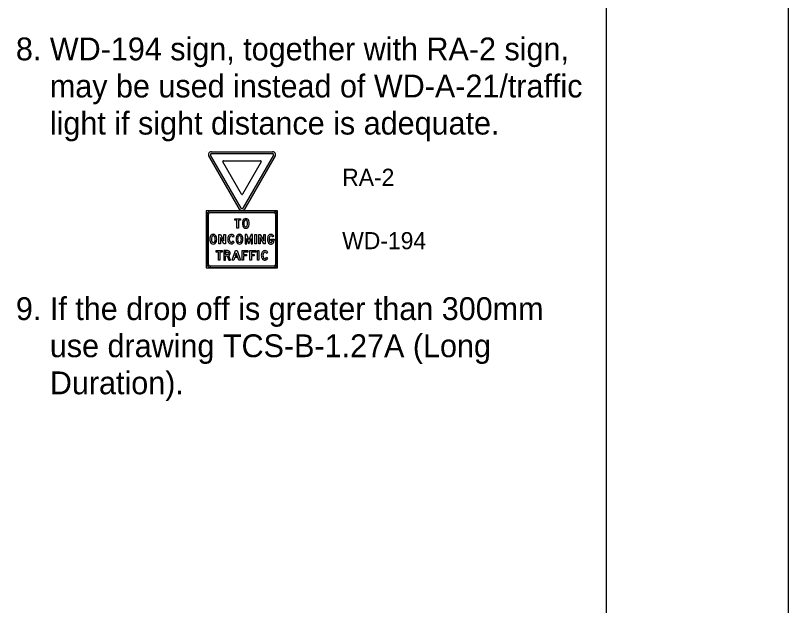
# Model space of a CAD drawing. Extents: x 1062 to 1288, y 239 to 518.
# Drawn here: x 1206.3 to 1287.6, y 312.1 to 374.1 of the extents above; entities that cross this region are included whole.
import ezdxf

# ---------------------------------------------------------------- set-up
doc = ezdxf.new("R2010")
doc.units = 0
for name, color, linetype in [('Level 1', 7, 'Continuous'), ('Level 17', 7, 'Continuous'), ('Level 60', 7, 'Continuous'), ('Level 61', 7, 'Continuous'), ('Level 62', 7, 'Continuous')]:
    doc.layers.add(name, color=color, linetype=linetype)

msp = doc.modelspace()

# ---------------------------------------------------------------- linework, layer by layer
at = {"layer": 'Level 1'}
for p, q in [((1226.352, 359.806), (1226.352, 359.806)), ((1233.835, 359.806), (1233.835, 359.806))]:
    msp.add_line(p, q, dxfattribs=at)
at = {"layer": 'Level 60'}
for p, q in [((1229.837, 353.769), (1226.609, 359.36)), ((1229.834, 353.743), (1226.61, 359.357)), ((1230.01, 353.869), (1226.782, 359.46)), ((1226.794, 359.623), (1226.798, 359.621)), ((1226.87, 359.807), (1226.874, 359.806)), ((1226.87, 359.806), (1233.317, 359.806)), ((1226.874, 359.806), (1233.322, 359.806)), ((1226.874, 359.606), (1233.322, 359.606)), ((1233.405, 359.46), (1230.186, 353.869)), ((1233.577, 359.357), (1230.347, 353.744)), ((1233.579, 359.36), (1230.359, 353.769)), ((1230.037, 355.338), (1228.074, 358.742)), ((1228.136, 358.849), (1232.051, 358.849)), ((1232.113, 358.742), (1230.161, 355.338)), ((1229.13, 350.849), (1229.28, 350.909)), ((1229.28, 350.329), (1229.13, 350.389)), ((1229.13, 350.389), (1229.13, 350.389)), ((1233.45, 350.899), (1233.3, 350.849)), ((1233.3, 350.849), (1233.3, 350.849)), ((1228.58, 349.009), (1228.35, 349.009)), ((1232.66, 349.149), (1232.81, 349.209)), ((1232.81, 348.629), (1232.66, 348.689)), ((1232.66, 348.689), (1232.66, 348.689))]:
    msp.add_line(p, q, dxfattribs=at)
for points in [[(1287.562, 517.932), (1071.562, 517.932), (1071.562, 238.932), (1287.562, 238.932)], [(1268.436, 507.123), (1081.562, 507.123), (1081.562, 249.741), (1268.436, 249.741)], [(1229.95, 352.769), (1229.95, 352.609), (1229.72, 352.609), (1229.72, 351.769), (1229.56, 351.769), (1229.56, 352.609), (1229.33, 352.609), (1229.33, 352.769)], [(1227.67, 350.109), (1227.67, 351.109), (1227.83, 351.109), (1228.2, 350.439), (1228.2, 351.109), (1228.36, 351.109), (1228.36, 350.109), (1228.2, 350.109), (1227.83, 350.779), (1227.83, 350.109)], [(1230.43, 350.109), (1230.59, 350.109), (1230.59, 350.699), (1230.82, 350.109), (1231.05, 350.699), (1231.05, 350.109), (1231.21, 350.109), (1231.21, 351.109), (1231.04, 351.109), (1230.82, 350.549), (1230.6, 351.109), (1230.43, 351.109)], [(1231.45, 351.109), (1231.61, 351.109), (1231.61, 350.109), (1231.45, 350.109)], [(1231.85, 350.109), (1231.85, 351.109), (1232.01, 351.109), (1232.38, 350.439), (1232.38, 351.109), (1232.54, 351.109), (1232.54, 350.109), (1232.38, 350.109), (1232.01, 350.779), (1232.01, 350.109)], [(1228, 349.409), (1228, 349.249), (1227.77, 349.249), (1227.77, 348.409), (1227.61, 348.409), (1227.61, 349.249), (1227.38, 349.249), (1227.38, 349.409)], [(1229.33, 348.679), (1229.23, 348.409), (1229.06, 348.409), (1229.4, 349.409), (1229.58, 349.409), (1229.92, 348.409), (1229.75, 348.409), (1229.65, 348.679)], [(1229.38, 348.839), (1229.6, 348.839), (1229.49, 349.159)], [(1230.72, 349.409), (1230.72, 349.249), (1230.26, 349.249), (1230.26, 349.009), (1230.56, 349.009), (1230.56, 348.849), (1230.26, 348.849), (1230.26, 348.409), (1230.1, 348.409), (1230.1, 349.409)], [(1231.54, 349.409), (1231.54, 349.249), (1231.08, 349.249), (1231.08, 349.009), (1231.37, 349.009), (1231.37, 348.849), (1231.08, 348.849), (1231.08, 348.409), (1230.92, 348.409), (1230.92, 349.409)], [(1231.72, 349.409), (1231.88, 349.409), (1231.88, 348.409), (1231.72, 348.409)]]:
    msp.add_lwpolyline(points, close=True, dxfattribs=at)
for points in [[(1233.3, 350.459), (1233.12, 350.459), (1233.12, 350.619), (1233.46, 350.619), (1233.46, 350.459)], [(1228.58, 349.409), (1228.19, 349.409), (1228.19, 348.409), (1228.35, 348.409), (1228.35, 348.849), (1228.54, 348.849)], [(1228.35, 349.009), (1228.35, 349.249), (1228.58, 349.249)], [(1228.54, 348.849), (1228.7, 348.409), (1228.88, 348.409), (1228.7, 348.879)]]:
    msp.add_lwpolyline(points, dxfattribs=at)
for centre, radius, start, end in [((1226.87, 359.507), 0.3, 90, 209.98927), ((1226.869, 359.506), 0.3, 90, 209.86734), ((1226.87, 359.507), 0.0997, 90, 209.98927), ((1233.316, 359.506), 0.3, 330.08336, 90), ((1233.321, 359.507), 0.3, 330.03077, 90), ((1233.321, 359.507), 0.0997, 330.03077, 90), ((1228.135, 358.777), 0.0716, 90, 209.98092), ((1232.051, 358.777), 0.0716, 330.17071, 90), ((1230.099, 355.373), 0.0716, 209.98036, 330.16989), ((1230.09, 353.898), 0.3, 211.17428, 328.87318), ((1230.097, 353.916), 0.3, 210.00132, 330.04133), ((1230.097, 353.916), 0.0997, 210.00132, 330.04133), ((1231.16, 352.28), 1.026, 166.05854, 180.2879), ((1231.16, 352.269), 1.026, 179.7121, 193.94146), ((1230.493, 352.45), 0.338, 90.40152, 166.9064), ((1230.493, 352.099), 0.338, 193.0936, 269.59848), ((1231.047, 352.293), 0.753, 162.59619, 181.38244), ((1231.047, 352.256), 0.753, 178.61757, 197.40381), ((1230.486, 352.46), 0.167, 88.23262, 159.96856), ((1230.486, 352.088), 0.167, 200.03143, 271.76738), ((1230.489, 352.45), 0.338, 13.0936, 89.59848), ((1230.496, 352.46), 0.167, 20.03143, 91.76738), ((1230.496, 352.088), 0.167, 268.23262, 339.96856), ((1230.489, 352.099), 0.338, 270.40152, 346.9064), ((1229.935, 352.293), 0.753, 358.61757, 17.40381), ((1229.935, 352.256), 0.753, 342.59619, 1.38244), ((1229.822, 352.28), 1.026, 359.7121, 13.94146), ((1229.822, 352.269), 1.026, 346.05854, 0.2879), ((1227.742, 350.617), 1.026, 166.05854, 180.2879), ((1227.742, 350.606), 1.026, 179.7121, 193.94146), ((1227.076, 350.787), 0.338, 90.40152, 166.9064), ((1227.076, 350.436), 0.338, 193.0936, 269.59848), ((1227.63, 350.63), 0.753, 162.59619, 181.38244), ((1227.63, 350.593), 0.753, 178.61757, 197.40381), ((1227.068, 350.798), 0.167, 88.23262, 159.96856), ((1227.068, 350.425), 0.167, 200.03143, 271.76738), ((1227.071, 350.787), 0.338, 13.0936, 89.59848), ((1227.079, 350.798), 0.167, 20.03143, 91.76738), ((1227.079, 350.425), 0.167, 268.23262, 339.96856), ((1227.071, 350.436), 0.338, 270.40152, 346.9064), ((1226.517, 350.63), 0.753, 358.61757, 17.40381), ((1226.517, 350.593), 0.753, 342.59619, 1.38244), ((1226.405, 350.617), 1.026, 359.7121, 13.94146), ((1226.405, 350.606), 1.026, 346.05854, 0.2879), ((1229.263, 350.619), 0.666, 149.79441, 180.51978), ((1229.263, 350.607), 0.666, 179.48022, 210.20559), ((1228.972, 350.791), 0.328, 21.11364, 150.27929), ((1229.229, 350.63), 0.47, 149.9866, 182.06213), ((1229.229, 350.596), 0.47, 177.93787, 210.0134), ((1228.972, 350.791), 0.168, 20.91519, 153.75348), ((1228.971, 350.432), 0.165, 205.38308, 344.75942), ((1230.497, 350.617), 1.026, 166.05854, 180.2879), ((1230.497, 350.606), 1.026, 179.7121, 193.94146), ((1229.831, 350.787), 0.338, 90.40152, 166.9064), ((1229.831, 350.436), 0.338, 193.0936, 269.59848), ((1230.385, 350.63), 0.753, 162.59619, 181.38244), ((1230.385, 350.593), 0.753, 178.61757, 197.40381), ((1229.823, 350.798), 0.167, 88.23262, 159.96856), ((1229.823, 350.425), 0.167, 200.03143, 271.76738), ((1229.826, 350.787), 0.338, 13.0936, 89.59848), ((1229.834, 350.798), 0.167, 20.03143, 91.76738), ((1229.834, 350.425), 0.167, 268.23262, 339.96856), ((1229.826, 350.436), 0.338, 270.40152, 346.9064), ((1229.272, 350.63), 0.753, 358.61757, 17.40381), ((1229.272, 350.593), 0.753, 342.59619, 1.38244), ((1229.16, 350.617), 1.026, 359.7121, 13.94146), ((1229.16, 350.606), 1.026, 346.05854, 0.2879), ((1233.51, 350.633), 0.735, 152.12407, 180.46122), ((1233.603, 350.602), 0.828, 178.25787, 201.30327), ((1233.138, 350.793), 0.332, 19.1763, 146.51388), ((1233.669, 350.609), 0.732, 159.35803, 201.1357), ((1233.138, 350.798), 0.169, 17.57516, 156.04499), ((1233.13, 350.421), 0.165, 262.12821, 336.90581), ((1232.782, 350.482), 0.515, 345.94617, 357.72968), ((1232.622, 350.514), 0.838, 345.82478, 356.40702), ((1228.97, 350.431), 0.324, 209.36901, 341.99271), ((1233.124, 350.407), 0.311, 199.87083, 284.58143), ((1233.117, 350.399), 0.142, 202.75759, 266.19325), ((1233.157, 350.392), 0.29, 278.98321, 343.25097), ((1228.576, 349.13), 0.279, 296.74606, 88.94876), ((1228.573, 349.127), 0.122, 273.9939, 86.00609), ((1232.792, 348.914), 0.666, 149.79441, 180.51978), ((1232.792, 348.902), 0.666, 179.48022, 210.20559), ((1232.501, 349.086), 0.328, 21.11364, 150.27929), ((1232.758, 348.925), 0.47, 149.9866, 182.06213), ((1232.758, 348.891), 0.47, 177.93787, 210.0134), ((1232.501, 349.085), 0.168, 20.91519, 153.75348), ((1232.499, 348.726), 0.324, 209.36901, 341.99271), ((1232.5, 348.726), 0.165, 205.38308, 344.75942)]:
    msp.add_arc(centre, radius, start, end, dxfattribs=at)
at = {"layer": 'Level 61'}
for p, q in [((1230.49, 352.619), (1230.49, 352.779)), ((1230.49, 352.779), (1230.49, 352.619)), ((1230.49, 352.619), (1230.49, 352.619)), ((1227.07, 350.959), (1227.07, 351.119)), ((1227.07, 351.119), (1227.07, 350.959)), ((1227.07, 350.959), (1227.07, 350.959)), ((1229.13, 350.849), (1229.28, 350.909)), ((1229.28, 350.329), (1229.13, 350.389)), ((1229.13, 350.389), (1229.13, 350.389)), ((1229.83, 350.959), (1229.83, 351.119)), ((1229.83, 351.119), (1229.83, 350.959)), ((1229.83, 350.959), (1229.83, 350.959)), ((1233.45, 350.899), (1233.3, 350.849)), ((1233.3, 350.849), (1233.3, 350.849)), ((1232.66, 349.149), (1232.81, 349.209)), ((1232.81, 348.629), (1232.66, 348.689)), ((1232.66, 348.689), (1232.66, 348.689))]:
    msp.add_line(p, q, dxfattribs=at)
for points in [[(1229.95, 352.769), (1229.95, 352.609), (1229.72, 352.609), (1229.72, 351.769), (1229.56, 351.769), (1229.56, 352.609), (1229.33, 352.609), (1229.33, 352.769)], [(1227.67, 350.109), (1227.67, 351.109), (1227.83, 351.109), (1228.2, 350.439), (1228.2, 351.109), (1228.36, 351.109), (1228.36, 350.109), (1228.2, 350.109), (1227.83, 350.779), (1227.83, 350.109)], [(1230.43, 350.109), (1230.59, 350.109), (1230.59, 350.699), (1230.82, 350.109), (1231.05, 350.699), (1231.05, 350.109), (1231.21, 350.109), (1231.21, 351.109), (1231.04, 351.109), (1230.82, 350.549), (1230.6, 351.109), (1230.43, 351.109)], [(1231.45, 351.109), (1231.61, 351.109), (1231.61, 350.109), (1231.45, 350.109)], [(1231.85, 350.109), (1231.85, 351.109), (1232.01, 351.109), (1232.38, 350.439), (1232.38, 351.109), (1232.54, 351.109), (1232.54, 350.109), (1232.38, 350.109), (1232.01, 350.779), (1232.01, 350.109)], [(1228, 349.409), (1228, 349.249), (1227.77, 349.249), (1227.77, 348.409), (1227.61, 348.409), (1227.61, 349.249), (1227.38, 349.249), (1227.38, 349.409)], [(1229.06, 348.409), (1229.4, 349.409), (1229.58, 349.409), (1229.92, 348.409), (1229.75, 348.409), (1229.49, 349.159), (1229.38, 348.839), (1229.6, 348.839), (1229.65, 348.679), (1229.33, 348.679), (1229.23, 348.409)], [(1230.72, 349.409), (1230.72, 349.249), (1230.26, 349.249), (1230.26, 349.009), (1230.56, 349.009), (1230.56, 348.849), (1230.26, 348.849), (1230.26, 348.409), (1230.1, 348.409), (1230.1, 349.409)], [(1231.54, 349.409), (1231.54, 349.249), (1231.08, 349.249), (1231.08, 349.009), (1231.37, 349.009), (1231.37, 348.849), (1231.08, 348.849), (1231.08, 348.409), (1230.92, 348.409), (1230.92, 349.409)], [(1231.72, 349.409), (1231.88, 349.409), (1231.88, 348.409), (1231.72, 348.409)]]:
    msp.add_lwpolyline(points, close=True, dxfattribs=at)
for points in [[(1233.3, 350.459), (1233.12, 350.459), (1233.12, 350.619), (1233.46, 350.619), (1233.46, 350.459)], [(1228.58, 349.009), (1228.35, 349.009), (1228.35, 349.409), (1228.19, 349.409), (1228.19, 348.409)], [(1228.19, 348.409), (1228.35, 348.409), (1228.35, 348.849), (1228.54, 348.849), (1228.7, 348.409), (1228.88, 348.409), (1228.7, 348.879)], [(1228.58, 349.409), (1228.35, 349.409), (1228.35, 349.249), (1228.58, 349.249)]]:
    msp.add_lwpolyline(points, dxfattribs=at)
for centre, radius, start, end in [((1231.16, 352.28), 1.026, 166.05854, 180.2879), ((1231.16, 352.269), 1.026, 179.7121, 193.94146), ((1230.493, 352.45), 0.338, 90.40152, 166.9064), ((1230.493, 352.099), 0.338, 193.0936, 269.59848), ((1231.047, 352.293), 0.753, 162.59619, 181.38243), ((1231.047, 352.256), 0.753, 178.61756, 197.40381), ((1230.486, 352.46), 0.167, 88.23262, 159.96857), ((1230.486, 352.088), 0.167, 200.03144, 271.76738), ((1230.489, 352.45), 0.338, 13.0936, 89.59002), ((1230.496, 352.46), 0.167, 20.03143, 91.75022), ((1230.496, 352.088), 0.167, 268.23263, 339.96857), ((1230.489, 352.099), 0.338, 270.40152, 346.9064), ((1229.935, 352.293), 0.753, 358.61756, 17.40381), ((1229.935, 352.256), 0.753, 342.59619, 1.38243), ((1229.822, 352.28), 1.026, 359.7121, 13.94146), ((1229.822, 352.269), 1.026, 346.05854, 0.2879), ((1227.742, 350.617), 1.026, 166.05854, 180.2879), ((1227.742, 350.606), 1.026, 179.7121, 193.94146), ((1227.076, 350.787), 0.338, 90.40152, 166.9064), ((1227.076, 350.436), 0.338, 193.0936, 269.59848), ((1227.63, 350.63), 0.753, 162.59619, 181.38243), ((1227.63, 350.593), 0.753, 178.61756, 197.40381), ((1227.068, 350.798), 0.167, 88.23262, 159.96857), ((1227.068, 350.425), 0.167, 200.03144, 271.76738), ((1227.071, 350.787), 0.338, 13.0936, 89.59002), ((1227.079, 350.798), 0.167, 20.03143, 91.75022), ((1227.079, 350.425), 0.167, 268.23263, 339.96857), ((1227.071, 350.436), 0.338, 270.40152, 346.9064), ((1226.517, 350.63), 0.753, 358.61756, 17.40381), ((1226.517, 350.593), 0.753, 342.59619, 1.38243), ((1226.405, 350.617), 1.026, 359.7121, 13.94146), ((1226.405, 350.606), 1.026, 346.05854, 0.2879), ((1229.263, 350.619), 0.666, 149.79441, 180.51978), ((1229.263, 350.607), 0.666, 179.48022, 210.20559), ((1228.972, 350.791), 0.328, 21.11364, 150.27929), ((1229.229, 350.63), 0.47, 149.9866, 182.06213), ((1229.229, 350.596), 0.47, 177.93787, 210.0134), ((1228.972, 350.791), 0.168, 20.91519, 153.75348), ((1228.971, 350.432), 0.165, 205.38308, 344.75942), ((1230.497, 350.617), 1.026, 166.05854, 180.2879), ((1230.497, 350.606), 1.026, 179.7121, 193.94146), ((1229.831, 350.787), 0.338, 90.40152, 166.9064), ((1229.831, 350.436), 0.338, 193.0936, 269.59848), ((1230.385, 350.63), 0.753, 162.59619, 181.38243), ((1230.385, 350.593), 0.753, 178.61756, 197.40381), ((1229.823, 350.798), 0.167, 88.23262, 159.96857), ((1229.823, 350.425), 0.167, 200.03144, 271.76738), ((1229.826, 350.787), 0.338, 13.0936, 89.59002), ((1229.834, 350.798), 0.167, 20.03143, 91.75022), ((1229.834, 350.425), 0.167, 268.23263, 339.96857), ((1229.826, 350.436), 0.338, 270.40152, 346.9064), ((1229.272, 350.63), 0.753, 358.61756, 17.40381), ((1229.272, 350.593), 0.753, 342.59619, 1.38243), ((1229.16, 350.617), 1.026, 359.7121, 13.94146), ((1229.16, 350.606), 1.026, 346.05854, 0.2879), ((1233.51, 350.633), 0.735, 152.12407, 180.46122), ((1233.603, 350.602), 0.828, 178.25787, 201.30327), ((1233.138, 350.793), 0.332, 19.1763, 146.51388), ((1233.669, 350.609), 0.732, 159.35803, 201.1357), ((1233.138, 350.798), 0.169, 17.57516, 156.04499), ((1233.13, 350.421), 0.165, 262.12821, 336.90581), ((1232.782, 350.482), 0.515, 345.94617, 357.72968), ((1232.622, 350.514), 0.838, 345.82478, 356.40702), ((1228.97, 350.431), 0.324, 209.36901, 341.99271), ((1233.124, 350.407), 0.311, 199.87083, 284.58143), ((1233.117, 350.399), 0.142, 202.75759, 266.19325), ((1233.157, 350.392), 0.29, 278.98321, 343.25097), ((1228.576, 349.13), 0.279, 296.74606, 88.94876), ((1228.573, 349.127), 0.122, 273.9939, 86.00609), ((1232.792, 348.914), 0.666, 149.79441, 180.51978), ((1232.792, 348.902), 0.666, 179.48022, 210.20559), ((1232.501, 349.086), 0.328, 21.11364, 150.27929), ((1232.758, 348.925), 0.47, 149.9866, 182.06213), ((1232.758, 348.891), 0.47, 177.93787, 210.0134), ((1232.501, 349.085), 0.168, 20.91519, 153.75348), ((1232.499, 348.726), 0.324, 209.36901, 341.99271), ((1232.5, 348.726), 0.165, 205.38308, 344.75942)]:
    msp.add_arc(centre, radius, start, end, dxfattribs=at)
at = {"layer": 'Level 62'}
for p, q in [((1233.84, 353.599), (1226.34, 353.599)), ((1226.34, 353.599), (1226.34, 347.599)), ((1226.39, 353.169), (1226.39, 348.029)), ((1226.54, 353.169), (1226.54, 348.029)), ((1233.41, 353.549), (1226.77, 353.549)), ((1233.41, 353.399), (1226.77, 353.399)), ((1233.64, 348.029), (1233.64, 353.169)), ((1233.79, 348.029), (1233.79, 353.169)), ((1233.84, 347.599), (1233.84, 353.599)), ((1230.49, 352.619), (1230.49, 352.779)), ((1230.49, 352.779), (1230.49, 352.619)), ((1230.49, 352.619), (1230.49, 352.619)), ((1227.07, 350.959), (1227.07, 351.119)), ((1227.07, 351.119), (1227.07, 350.959)), ((1227.07, 350.959), (1227.07, 350.959)), ((1229.13, 350.849), (1229.28, 350.909)), ((1229.28, 350.329), (1229.13, 350.389)), ((1229.13, 350.389), (1229.13, 350.389)), ((1229.83, 350.959), (1229.83, 351.119)), ((1229.83, 351.119), (1229.83, 350.959)), ((1229.83, 350.959), (1229.83, 350.959)), ((1233.45, 350.899), (1233.3, 350.849)), ((1233.3, 350.849), (1233.3, 350.849)), ((1232.66, 349.149), (1232.81, 349.209)), ((1232.81, 348.629), (1232.66, 348.689)), ((1232.66, 348.689), (1232.66, 348.689)), ((1226.34, 347.599), (1233.84, 347.599)), ((1226.77, 347.649), (1226.77, 347.799)), ((1226.77, 347.799), (1233.41, 347.799)), ((1226.77, 347.649), (1226.77, 347.799)), ((1226.77, 347.649), (1233.41, 347.649))]:
    msp.add_line(p, q, dxfattribs=at)
for points in [[(1229.95, 352.769), (1229.95, 352.609), (1229.72, 352.609), (1229.72, 351.769), (1229.56, 351.769), (1229.56, 352.609), (1229.33, 352.609), (1229.33, 352.769)], [(1227.67, 350.109), (1227.67, 351.109), (1227.83, 351.109), (1228.2, 350.439), (1228.2, 351.109), (1228.36, 351.109), (1228.36, 350.109), (1228.2, 350.109), (1227.83, 350.779), (1227.83, 350.109)], [(1230.43, 350.109), (1230.59, 350.109), (1230.59, 350.699), (1230.82, 350.109), (1231.05, 350.699), (1231.05, 350.109), (1231.21, 350.109), (1231.21, 351.109), (1231.04, 351.109), (1230.82, 350.549), (1230.6, 351.109), (1230.43, 351.109)], [(1231.45, 351.109), (1231.61, 351.109), (1231.61, 350.109), (1231.45, 350.109)], [(1231.85, 350.109), (1231.85, 351.109), (1232.01, 351.109), (1232.38, 350.439), (1232.38, 351.109), (1232.54, 351.109), (1232.54, 350.109), (1232.38, 350.109), (1232.01, 350.779), (1232.01, 350.109)], [(1228, 349.409), (1228, 349.249), (1227.77, 349.249), (1227.77, 348.409), (1227.61, 348.409), (1227.61, 349.249), (1227.38, 349.249), (1227.38, 349.409)], [(1229.06, 348.409), (1229.4, 349.409), (1229.58, 349.409), (1229.92, 348.409), (1229.75, 348.409), (1229.49, 349.159), (1229.38, 348.839), (1229.6, 348.839), (1229.65, 348.679), (1229.33, 348.679), (1229.23, 348.409)], [(1230.72, 349.409), (1230.72, 349.249), (1230.26, 349.249), (1230.26, 349.009), (1230.56, 349.009), (1230.56, 348.849), (1230.26, 348.849), (1230.26, 348.409), (1230.1, 348.409), (1230.1, 349.409)], [(1231.54, 349.409), (1231.54, 349.249), (1231.08, 349.249), (1231.08, 349.009), (1231.37, 349.009), (1231.37, 348.849), (1231.08, 348.849), (1231.08, 348.409), (1230.92, 348.409), (1230.92, 349.409)], [(1231.72, 349.409), (1231.88, 349.409), (1231.88, 348.409), (1231.72, 348.409)]]:
    msp.add_lwpolyline(points, close=True, dxfattribs=at)
for points in [[(1233.3, 350.459), (1233.12, 350.459), (1233.12, 350.619), (1233.46, 350.619), (1233.46, 350.459)], [(1228.58, 349.009), (1228.35, 349.009), (1228.35, 349.409), (1228.19, 349.409), (1228.19, 348.409)], [(1228.19, 348.409), (1228.35, 348.409), (1228.35, 348.849), (1228.54, 348.849), (1228.7, 348.409), (1228.88, 348.409), (1228.7, 348.879)], [(1228.58, 349.409), (1228.35, 349.409), (1228.35, 349.249), (1228.58, 349.249)]]:
    msp.add_lwpolyline(points, dxfattribs=at)
for centre, radius, start, end in [((1226.77, 353.167), 0.38, 90, 180), ((1226.77, 353.167), 0.23, 90, 180), ((1233.408, 353.167), 0.38, 0, 90), ((1233.408, 353.167), 0.23, 0, 90), ((1231.16, 352.28), 1.026, 166.05854, 180.2879), ((1231.16, 352.269), 1.026, 179.7121, 193.94146), ((1230.493, 352.45), 0.338, 90.40152, 166.9064), ((1230.493, 352.099), 0.338, 193.0936, 269.59848), ((1231.047, 352.293), 0.753, 162.59619, 181.38243), ((1231.047, 352.256), 0.753, 178.61756, 197.40381), ((1230.486, 352.46), 0.167, 88.23262, 159.96857), ((1230.486, 352.088), 0.167, 200.03144, 271.76738), ((1230.489, 352.45), 0.338, 13.0936, 89.59002), ((1230.496, 352.46), 0.167, 20.03143, 91.75022), ((1230.496, 352.088), 0.167, 268.23263, 339.96857), ((1230.489, 352.099), 0.338, 270.40152, 346.9064), ((1229.935, 352.293), 0.753, 358.61756, 17.40381), ((1229.935, 352.256), 0.753, 342.59619, 1.38243), ((1229.822, 352.28), 1.026, 359.7121, 13.94146), ((1229.822, 352.269), 1.026, 346.05854, 0.2879), ((1227.742, 350.617), 1.026, 166.05854, 180.2879), ((1227.742, 350.606), 1.026, 179.7121, 193.94146), ((1227.076, 350.787), 0.338, 90.40152, 166.9064), ((1227.076, 350.436), 0.338, 193.0936, 269.59848), ((1227.63, 350.63), 0.753, 162.59619, 181.38243), ((1227.63, 350.593), 0.753, 178.61756, 197.40381), ((1227.068, 350.798), 0.167, 88.23262, 159.96857), ((1227.068, 350.425), 0.167, 200.03144, 271.76738), ((1227.071, 350.787), 0.338, 13.0936, 89.59002), ((1227.079, 350.798), 0.167, 20.03143, 91.75022), ((1227.079, 350.425), 0.167, 268.23263, 339.96857), ((1227.071, 350.436), 0.338, 270.40152, 346.9064), ((1226.517, 350.63), 0.753, 358.61756, 17.40381), ((1226.517, 350.593), 0.753, 342.59619, 1.38243), ((1226.405, 350.617), 1.026, 359.7121, 13.94146), ((1226.405, 350.606), 1.026, 346.05854, 0.2879), ((1229.263, 350.619), 0.666, 149.79441, 180.51978), ((1229.263, 350.607), 0.666, 179.48022, 210.20559), ((1228.972, 350.791), 0.328, 21.11364, 150.27929), ((1229.229, 350.63), 0.47, 149.9866, 182.06213), ((1229.229, 350.596), 0.47, 177.93787, 210.0134), ((1228.972, 350.791), 0.168, 20.91519, 153.75348), ((1228.971, 350.432), 0.165, 205.38308, 344.75942), ((1230.497, 350.617), 1.026, 166.05854, 180.2879), ((1230.497, 350.606), 1.026, 179.7121, 193.94146), ((1229.831, 350.787), 0.338, 90.40152, 166.9064), ((1229.831, 350.436), 0.338, 193.0936, 269.59848), ((1230.385, 350.63), 0.753, 162.59619, 181.38243), ((1230.385, 350.593), 0.753, 178.61756, 197.40381), ((1229.823, 350.798), 0.167, 88.23262, 159.96857), ((1229.823, 350.425), 0.167, 200.03144, 271.76738), ((1229.826, 350.787), 0.338, 13.0936, 89.59002), ((1229.834, 350.798), 0.167, 20.03143, 91.75022), ((1229.834, 350.425), 0.167, 268.23263, 339.96857), ((1229.826, 350.436), 0.338, 270.40152, 346.9064), ((1229.272, 350.63), 0.753, 358.61756, 17.40381), ((1229.272, 350.593), 0.753, 342.59619, 1.38243), ((1229.16, 350.617), 1.026, 359.7121, 13.94146), ((1229.16, 350.606), 1.026, 346.05854, 0.2879), ((1233.51, 350.633), 0.735, 152.12407, 180.46122), ((1233.603, 350.602), 0.828, 178.25787, 201.30327), ((1233.138, 350.793), 0.332, 19.1763, 146.51388), ((1233.669, 350.609), 0.732, 159.35803, 201.1357), ((1233.138, 350.798), 0.169, 17.57516, 156.04499), ((1233.13, 350.421), 0.165, 262.12821, 336.90581), ((1232.782, 350.482), 0.515, 345.94617, 357.72968), ((1232.622, 350.514), 0.838, 345.82478, 356.40702), ((1228.97, 350.431), 0.324, 209.36901, 341.99271), ((1233.124, 350.407), 0.311, 199.87083, 284.58143), ((1233.117, 350.399), 0.142, 202.75759, 266.19325), ((1233.157, 350.392), 0.29, 278.98321, 343.25097), ((1228.576, 349.13), 0.279, 296.74606, 88.94876), ((1228.573, 349.127), 0.122, 273.9939, 86.00609), ((1232.792, 348.914), 0.666, 149.79441, 180.51978), ((1232.792, 348.902), 0.666, 179.48022, 210.20559), ((1232.501, 349.086), 0.328, 21.11364, 150.27929), ((1232.758, 348.925), 0.47, 149.9866, 182.06213), ((1232.758, 348.891), 0.47, 177.93787, 210.0134), ((1232.501, 349.085), 0.168, 20.91519, 153.75348), ((1226.77, 348.029), 0.38, 180, 270), ((1226.77, 348.029), 0.23, 180, 270), ((1232.499, 348.726), 0.324, 209.36901, 341.99271), ((1232.5, 348.726), 0.165, 205.38308, 344.75942), ((1233.408, 348.029), 0.38, 270, 0), ((1233.408, 348.029), 0.23, 270, 0)]:
    msp.add_arc(centre, radius, start, end, dxfattribs=at)

# ---------------------------------------------------------------- texts
at = {"layer": 'Level 17'}
for s, p in [('RA-2', (1240.629, 356.221)), ('WD-194', (1240.629, 349.561))]:
    msp.add_text(s, height=1.8, dxfattribs=at).set_placement(p)
at = {"layer": 'Level 60'}
for s, p in [('8. WD-194 sign, together with RA-2 sign,', (1206.321, 369.412)), ('    may be used instead of WD-A-21/traffic ', (1206.321, 365.512)), ('    light if sight distance is adequate.', (1206.321, 361.612)), ('9. If the drop off is greater than 300mm ', (1206.321, 342.112)), ('    use drawing TCS-B-1.27A (Long ', (1206.321, 338.212)), ('    Duration).', (1206.321, 334.312))]:
    msp.add_text(s, height=2.4, dxfattribs=at).set_placement(p)

doc.saveas('drawing.dxf')
